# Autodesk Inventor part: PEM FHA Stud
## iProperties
Author: John A. Hunter
Shininess: 64.0
Angle Display Precision: 2
Document Length Units: 11272
Document Angle Units: 11286
Document Time Units: 11279
Document Mass Units: 11290
Document Length Units Precision: 3
Document Angle Units Precision: 2
Compacted: True
PropertySet Name: _Private Model Information
Created: 2002-08
Part Number: PEM FHA Stud
Material: Aluminum-6061
Description: FHA-632-8
Document SubType Name: Modeling
Designer: John A. Hunter
Control State: 0
Master: False
Checked Out: False
PropertySet Name: Design Tracking Control
Density: 0.0
Volumn: 0.0
Area: 0.0
PropertySet Name: Model Information
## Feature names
1. Extrusion1
2. Extrusion2
